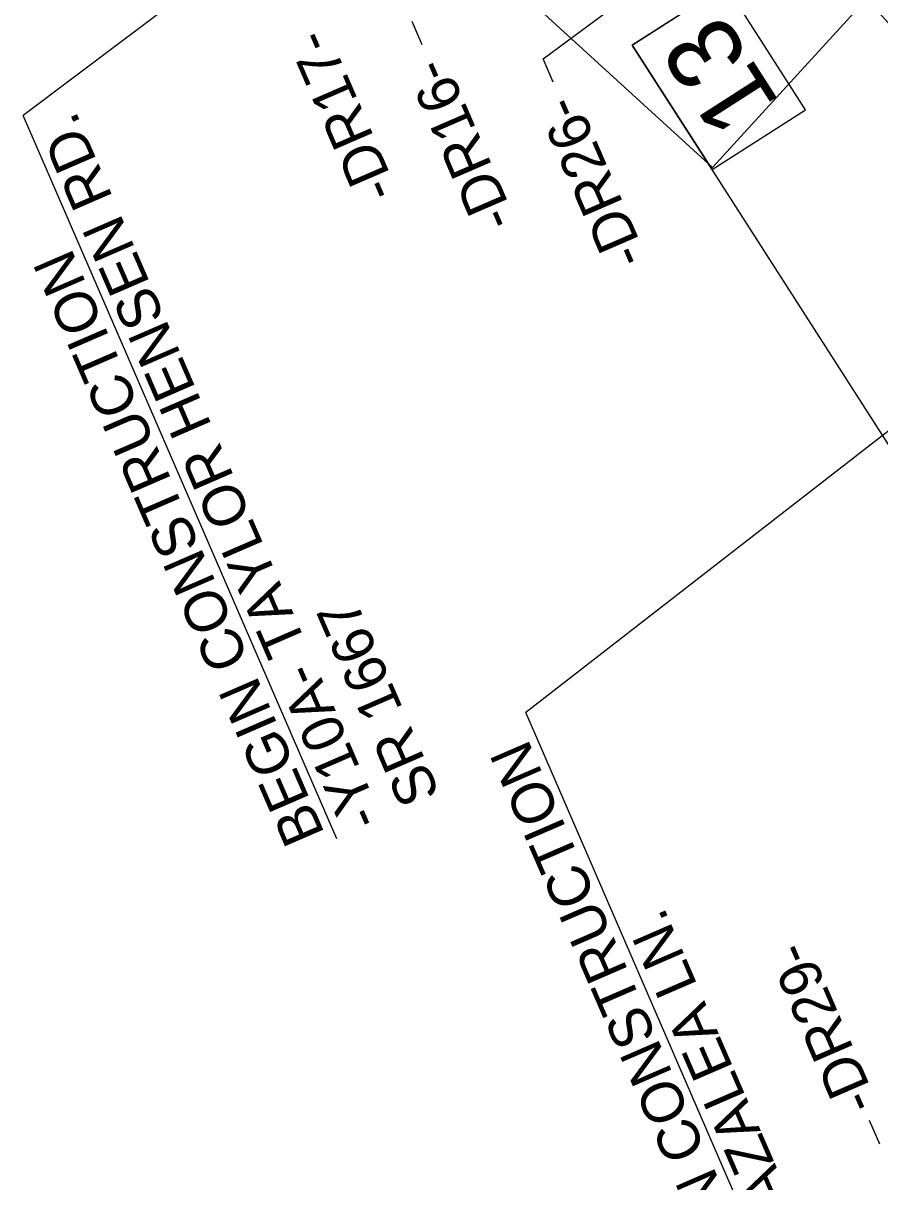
# Model space of a CAD drawing. Extents: x 442728 to 492797, y 479541 to 511293.
# Drawn here: x 475292 to 477236, y 497516 to 500146 of the extents above; entities that cross this region are included whole.
import ezdxf

# ---------------------------------------------------------------- set-up
doc = ezdxf.new("R2010")
doc.units = 0
for name, color, linetype in [('Prop DSN Text', 7, 'Continuous'), ('Prop Shade Light', 7, 'Continuous'), ('Sheet Plan Layout CELL', 7, 'Continuous')]:
    doc.layers.add(name, color=color, linetype=linetype)

msp = doc.modelspace()

# ---------------------------------------------------------------- linework, layer by layer
at = {"layer": 'Prop DSN Text'}
for p, q in [((476332.4, 500720.1), (475292.3, 499935.8)), ((476472.1, 500064.6), (476897.9, 500380.3)), ((476197.7, 500096.3), (476174.7, 500149.3)), ((476495.1, 500011.5), (476472.1, 500064.6)), ((475337.4, 499831.6), (475292.3, 499935.8)), ((476004, 498294.4), (475337.4, 499831.6)), ((477506.2, 499414.3), (476433.1, 498581)), ((476478.3, 498476.8), (476433.1, 498581)), ((477040.5, 497180.3), (476478.3, 498476.8)), ((477236, 497601.6), (477213, 497654.7))]:
    msp.add_line(p, q, dxfattribs=at)
at = {"layer": 'Prop Shade Light'}
msp.add_arc((475172.8, 498218.8), 2838, 38.3571, 44.2663, dxfattribs=at)
at = {"layer": 'Sheet Plan Layout CELL'}
for points in [[(477564.9, 500593.5), (476856.6, 499818.3), (476026.1, 500577.2), (476026.1, 500577.2), (475749.3, 500830.1), (476457.6, 501605.3)], [(478368.3, 499400.5), (477484.4, 498833.4), (476877, 499780.3), (476877, 499780.4), (476674.6, 500096), (477558.3, 500662.9)], [(477067.8, 499949.3), (476886.6, 500231.9), (476674.6, 500096), (476855.8, 499813.4)]]:
    msp.add_lwpolyline(points, close=True, dxfattribs=at)

# ---------------------------------------------------------------- texts
at = {"layer": 'Prop DSN Text'}
for s, height, p in [('-DR17- ', 94.92, (476142.5, 499763.8)), ('-DR16- ', 94.92, (476411.1, 499697.6)), ('-DR26- ', 94.92, (476708.5, 499612.9)), ('-Y10A- TAYLOR HENSEN RD.', 94.918, (476108.6, 498338.4)), ('BEGIN CONSTRUCTION', 94.918, (475977.5, 498305.6)), ('SR 1667', 94.92, (476239.2, 498395)), ('BEGIN CONSTRUCTION', 94.918, (477014, 497191.5)), ('-Y8- AZALEA LN.', 94.918, (477140.6, 497229.9)), ('-DR29- ', 94.92, (477231.8, 497693.5))]:
    msp.add_text(s, height=height, rotation=113.4424, dxfattribs=at).set_placement(p)
at = {"layer": 'Sheet Plan Layout CELL'}
msp.add_text('13', height=168.74, rotation=122.677, dxfattribs=at).set_placement((477011.5, 499962.9))

doc.saveas('drawing.dxf')
